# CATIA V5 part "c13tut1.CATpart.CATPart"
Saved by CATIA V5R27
Part number: Part1
Bounding box of the stored display mesh (mm): x -49.99 to 34.99, y -44.302 to 44.302, z 0 to 30
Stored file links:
  E:\_Deepak\2017_Deepak\CATIA\Resources\Tutorial Files\Tutorials\c13_catia_v5_6r2016_tut\c13tut1\c13tut1.CATpart.CATPart
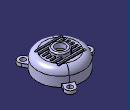
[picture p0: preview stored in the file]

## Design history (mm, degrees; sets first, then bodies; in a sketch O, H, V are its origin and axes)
Body1 (main body)
  Sketch1 on yz-plane, origin (0, 0, 0), H (0, 1, 0), V (0, 0, 1)
    line L1 (0, 0) -> (35, 0)
    line L2 (35, 0) -> (35, 15)
    arc A1 centre (25, 15) radius 10 from (35, 15) to (25, 25) ccw
    line L3 (25, 25) -> (0, 25)
    point P5 (0, 25)
    line L4 (0, 25) -> (0, 0)
    axis line L5 (0, 70.1891) -> (0, -36.6898)
    point P6 (0, 70.1891)
    radius about axis L2 L5 = 35
    distance L1 L3 = 25
    radius A1 = 10
    horizontal: L1 H
    vertical: L2 V, L4 V, L5 V
    tangency: A1 L2, L3 A1
    coincidence: P5 V, P6 V
  Shaft1: profile Sketch1, axis Sketch1.L5, angle 360
  Shell1: ExtOffset 0, Face face of Shaft1, IntOffset 2.5
  Sketch2 on face of Shaft1, origin (0, 0, 0), H (1, 0, 0), V (0, -1, 0)
    projected circle E1 centre (0, 0) radius 35 from edge [face of Shaft1 | face of Shaft1]
    projected arc E2 centre (0, 0) radius 35 from (-34.187, 7.5) to (-34.187, -7.5) ccw from edge [face of Shaft1 | face of Shaft1]
    point P1 (-34.187, 7.5)
    line L1 (-34.187, 7.5) -> (-42.5, 7.5)
    arc A1 centre (-42.5, 0) radius 7.5 from (-42.5, 7.5) to (-42.5, -7.5) ccw
    point P3 (-42.5, 0)
    line L2 (-42.5, -7.5) -> (-34.187, -7.5)
    point P5 (-34.187, -7.5)
    circle A2 centre (-42.5, 0) radius 3.75
    distance P3 V = 42.5
    radius A1 = 7.5
    radius A2 = 3.75
    coincidence: P1 E1, P5 E1, P3 H
    horizontal: L1 H, L2 H
    tangency: A1 L1, L2 A1
  Pad1: profile Sketch2, direction (0, 0, 1), length 5
  CircPattern1: of Pad1, instances 3, angular step 120 {= 360.0*1 deg/CircPattern1.AngularNumber}, axis from face of Shaft1
  Sketch3 on face of Shaft1, origin (0, 0, 25), H (1, 0, 0), V (0, 1, 0)
    construction line L1 (-20, -18) -> (20, -18)
    point P2 (20, -18)
    line L2 (-20, -16.25) -> (20, -16.25)
    line L3 (20, -19.75) -> (-20, -19.75)
    arc A1 centre (20, -18) radius 1.75 from (20, -16.25) to (20, -19.75) cw
    arc A2 centre (-20, -18) radius 1.75 from (-20, -19.75) to (-20, -16.25) cw
    length L1 = 40
    distance H L1 = 18
    distance P2 V = 20
    distance L3 L2 = 3.5
    horizontal: L1 H
    tangency: A1 L2, A2 L2, A1 L3, A2 L3
    parallelism: L1 L2
  Pocket1: profile Sketch3, direction (0, 0, -1), through (limit type 3)
  RectPattern1: of Pocket1, direction 1 instances 7, spacing 6, along yz-plane
  Sketch4 on yz-plane, origin (0, 0, 0), H (0, 1, 0), V (0, 0, 1)
    axis line L1 (0, 0) -> (0, 35.5018)
    point P2 (0, 22.5)
    line L2 (0, 22.5) -> (12.5, 22.5)
    line L3 (12.5, 22.5) -> (12.5, 28)
    arc A1 centre (10.5, 28) radius 2 from (12.5, 28) to (10.5, 30) ccw
    line L4 (10.5, 30) -> (0, 30)
    point P7 (0, 30)
    line L5 (0, 30) -> (0, 22.5)
    reference intersected line E1 (25, 22.5) -> (-25, 22.5) from face of Shell1
    radius about axis L3 L1 = 12.5
    distance L4 L2 = 7.5
    radius A1 = 2
    vertical: L1 V, L3 V, L5 V
    coincidence: P2 L1, P7 L1, L2 E1
    horizontal: L2 H, L4 H
    tangency: A1 L3, L4 A1
  Shaft2: profile Sketch4, axis Sketch4.L1, angle 360
  Sketch5 on face of Shaft2, origin (0, 0, 30), H (1, 0, 0), V (0, 1, 0)
    point P1 (0, 0)
    reference projected circle E1 centre (0, 0) radius 12.5 from edge [face of Shaft2 | face of Shaft2]
    concentricity: P1 E1
  Hole1: placed by Sketch5, at (0, 0, 30) direction (0, 0, -1), diameter 15, through (limit type 3)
